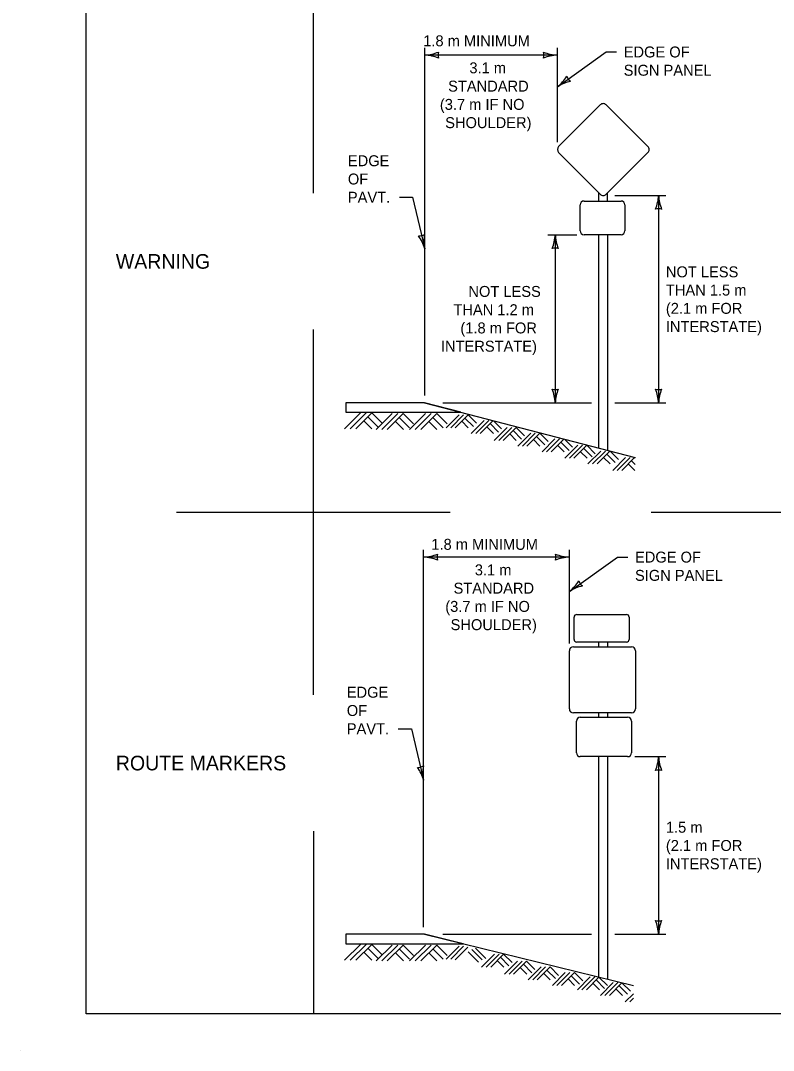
# Model space of a CAD drawing. Extents: x 49991.4 to 50021, y 49987.6 to 50011.4.
# Drawn here: x 49999.02 to 50003.15, y 49987.6 to 49993.24 of the extents above; entities that cross this region are included whole.
import ezdxf

# ---------------------------------------------------------------- set-up
doc = ezdxf.new("R2010")
doc.units = 0
for name, color, linetype in [('Level 1', 7, 'Continuous'), ('Level 2', 7, 'Continuous'), ('Level 3', 7, 'Continuous')]:
    doc.layers.add(name, color=color, linetype=linetype)

msp = doc.modelspace()

# ---------------------------------------------------------------- linework, layer by layer
at = {"layer": 'Level 1'}
for p, q in [((50001.9717, 49992.5484), (50002.2003, 49992.7772)), ((50002.2321, 49992.7772), (50002.461, 49992.5484)), ((50002.2003, 49992.2877), (50001.9717, 49992.5166)), ((50002.461, 49992.5166), (50002.2321, 49992.2877)), ((50002.1919, 49992.2506), (50002.1919, 49992.2961)), ((50002.2405, 49992.2506), (50002.2405, 49992.2961)), ((50002.0896, 49992.0878), (50002.0896, 49992.2291)), ((50002.1111, 49992.2506), (50002.3137, 49992.2506)), ((50002.3352, 49992.2291), (50002.3352, 49992.0878)), ((50002.3137, 49992.0663), (50002.1111, 49992.0663)), ((50002.1919, 49990.8971), (50002.1919, 49992.0663)), ((50002.2406, 49990.8844), (50002.2406, 49992.0663)), ((50000.7994, 49991.003), (50000.8867, 49991.0903)), ((50001.2376, 49991.1452), (50000.8056, 49991.1452)), ((50000.8056, 49991.1452), (50000.8056, 49991.0936)), ((50001.2376, 49991.1452), (50000.8056, 49991.1452)), ((50000.8056, 49991.1452), (50000.8056, 49991.0936)), ((50000.8056, 49991.0936), (50001.4364, 49991.0936)), ((50000.8056, 49991.0936), (50001.4363, 49991.0936)), ((50000.8301, 49991.003), (50000.9174, 49991.0903)), ((50000.8605, 49991.003), (50000.9478, 49991.0903)), ((50000.9478, 49991.0903), (50001.0047, 49991.0335)), ((50001.2379, 49991.1452), (50002.3914, 49990.8452)), ((50001.4363, 49991.0936), (50001.2379, 49991.1452)), ((50001.4361, 49991.0936), (50001.4361, 49991.0936)), ((50000.9047, 49991.047), (50000.9488, 49991.003)), ((50000.9264, 49991.0687), (50000.9831, 49991.0121)), ((50000.9722, 49990.9993), (50001.0595, 49991.0867)), ((50001.0029, 49990.9993), (50001.0902, 49991.0867)), ((50001.0334, 49990.9993), (50001.1207, 49991.0867)), ((50001.0775, 49991.0434), (50001.1216, 49990.9993)), ((50001.0991, 49991.0651), (50001.1558, 49991.0084)), ((50001.1207, 49991.0867), (50001.1776, 49991.0299)), ((50001.1557, 49990.9993), (50001.243, 49991.0867)), ((50001.1864, 49990.9993), (50001.2737, 49991.0867)), ((50001.2168, 49990.9993), (50001.3042, 49991.0867)), ((50001.261, 49991.0434), (50001.3051, 49990.9993)), ((50001.2826, 49991.0651), (50001.3393, 49991.0084)), ((50001.3042, 49991.0867), (50001.3611, 49991.0299)), ((50001.356, 49991.0088), (50001.4267, 49991.0795)), ((50001.3808, 49991.0088), (50001.4515, 49991.0795)), ((50001.4054, 49991.0088), (50001.4761, 49991.0795)), ((50001.4412, 49991.0446), (50001.4771, 49991.0088)), ((50001.4587, 49991.0622), (50001.5048, 49991.0162)), ((50001.4761, 49991.0795), (50001.5222, 49991.0335)), ((50001.4934, 49990.9781), (50001.5641, 49991.0488)), ((50001.5182, 49990.9781), (50001.5889, 49991.0488)), ((50001.5428, 49990.9781), (50001.6126, 49991.0477)), ((50001.6155, 49991.047), (50001.6596, 49991.0028)), ((50001.5786, 49991.0138), (50001.6145, 49990.9781)), ((50001.5962, 49991.0315), (50001.6422, 49990.9855)), ((50001.6191, 49990.9398), (50001.6898, 49991.0105)), ((50001.644, 49990.9398), (50001.7147, 49991.0105)), ((50001.6686, 49990.9398), (50001.7393, 49991.0105)), ((50001.722, 49990.9931), (50001.7679, 49990.9472)), ((50001.7393, 49991.0105), (50001.7854, 49990.9645)), ((50001.7482, 49990.908), (50001.8189, 49990.9788)), ((50001.7732, 49990.908), (50001.8439, 49990.9788)), ((50001.7978, 49990.908), (50001.8685, 49990.9788)), ((50001.8685, 49990.9788), (50001.9146, 49990.9327)), ((50001.7044, 49990.9756), (50001.7402, 49990.9398)), ((50001.8336, 49990.9437), (50001.8693, 49990.908)), ((50001.851, 49990.9614), (50001.897, 49990.9154)), ((50001.881, 49990.8776), (50001.9517, 49990.9483)), ((50001.9058, 49990.8776), (50001.9767, 49990.9483)), ((50001.9306, 49990.8776), (50002, 49990.947)), ((50001.9838, 49990.9308), (50002.0298, 49990.8851)), ((50002.0035, 49990.9461), (50002.0474, 49990.9024)), ((50001.9664, 49990.9132), (50002.002, 49990.8776)), ((50002.0065, 49990.8418), (50002.0772, 49990.9126)), ((50002.0315, 49990.8418), (50002.1022, 49990.9126)), ((50002.056, 49990.8418), (50002.1267, 49990.9126)), ((50002.0918, 49990.8776), (50002.1275, 49990.8418)), ((50002.1092, 49990.8951), (50002.1553, 49990.8492)), ((50002.1267, 49990.9126), (50002.1729, 49990.8665)), ((50002.1328, 49990.8107), (50002.2035, 49990.8814)), ((50002.1576, 49990.8107), (50002.2284, 49990.8814)), ((50002.1822, 49990.8107), (50002.2529, 49990.8812)), ((50002.2356, 49990.864), (50002.2816, 49990.8181)), ((50002.2534, 49990.8811), (50002.2992, 49990.8355)), ((50002.2181, 49990.8464), (50002.2538, 49990.8107)), ((50002.2681, 49990.7748), (50002.3388, 49990.8455)), ((50002.2931, 49990.7748), (50002.3638, 49990.8455)), ((50002.3176, 49990.7748), (50002.3884, 49990.8455)), ((50002.3535, 49990.8105), (50002.3893, 49990.7748)), ((50002.3709, 49990.8281), (50002.3914, 49990.8076)), ((50002.3884, 49990.8455), (50002.3914, 49990.8425)), ((50002.0565, 49989.8499), (50002.0565, 49989.9711)), ((50002.0715, 49989.9861), (50002.3436, 49989.9861)), ((50002.3586, 49989.9711), (50002.3586, 49989.8499)), ((50002.0531, 49989.8098), (50002.3707, 49989.8098)), ((50002.3436, 49989.8349), (50002.0715, 49989.8349)), ((50002.192, 49989.8098), (50002.192, 49989.8349)), ((50002.2406, 49989.8098), (50002.2406, 49989.8349)), ((50002.0306, 49989.4698), (50002.0306, 49989.7873)), ((50002.3932, 49989.7873), (50002.3932, 49989.4698)), ((50002.3707, 49989.4473), (50002.0531, 49989.4473)), ((50002.0693, 49989.229), (50002.0693, 49989.4019)), ((50002.0908, 49989.4234), (50002.35, 49989.4234)), ((50002.192, 49989.4234), (50002.192, 49989.4473)), ((50002.2406, 49989.4234), (50002.2406, 49989.4473)), ((50002.3715, 49989.4019), (50002.3715, 49989.229)), ((50002.35, 49989.2075), (50002.0908, 49989.2075)), ((50002.192, 49988.0012), (50002.192, 49989.2075)), ((50002.2406, 49987.9893), (50002.2406, 49989.2075)), ((50001.2376, 49988.2345), (50000.8056, 49988.2345)), ((50000.8056, 49988.2345), (50000.8056, 49988.1828)), ((50001.2376, 49988.2345), (50000.8056, 49988.2345)), ((50000.8056, 49988.2345), (50000.8056, 49988.1828)), ((50001.2377, 49988.2345), (50002.3813, 49987.9549)), ((50001.4491, 49988.1828), (50001.2377, 49988.2345)), ((50000.7994, 49988.0922), (50000.8867, 49988.1796)), ((50000.8056, 49988.1828), (50001.4491, 49988.1828)), ((50000.8056, 49988.1828), (50001.4491, 49988.1828)), ((50000.8301, 49988.0922), (50000.9174, 49988.1796)), ((50000.8605, 49988.0922), (50000.9479, 49988.1796)), ((50000.9264, 49988.158), (50000.9832, 49988.1013)), ((50000.9479, 49988.1796), (50001.0047, 49988.1228)), ((50000.9722, 49988.0886), (50001.0596, 49988.1759)), ((50001.0029, 49988.0886), (50001.0902, 49988.1759)), ((50001.0334, 49988.0886), (50001.1207, 49988.1759)), ((50001.1207, 49988.1759), (50001.1776, 49988.1192)), ((50001.1557, 49988.0886), (50001.2431, 49988.1759)), ((50001.1864, 49988.0886), (50001.2737, 49988.1759)), ((50001.2169, 49988.0886), (50001.3042, 49988.1759)), ((50001.3042, 49988.1759), (50001.3611, 49988.1192)), ((50001.356, 49988.0981), (50001.4267, 49988.1688)), ((50001.3808, 49988.0981), (50001.4515, 49988.1688)), ((50001.4044, 49988.0941), (50001.4751, 49988.1648)), ((50001.5157, 49988.1583), (50001.5726, 49988.1016)), ((50000.9047, 49988.1363), (50000.9488, 49988.0922)), ((50001.0775, 49988.1326), (50001.1217, 49988.0886)), ((50001.0991, 49988.1543), (50001.1559, 49988.0977)), ((50001.261, 49988.1326), (50001.3051, 49988.0886)), ((50001.2826, 49988.1543), (50001.3394, 49988.0977)), ((50001.4762, 49988.1379), (50001.5331, 49988.0812)), ((50001.4957, 49988.1519), (50001.5526, 49988.0952)), ((50001.5503, 49988.0553), (50001.621, 49988.126)), ((50001.5751, 49988.0553), (50001.6458, 49988.126)), ((50001.5998, 49988.0553), (50001.6706, 49988.126)), ((50001.6531, 49988.1086), (50001.6991, 49988.0627)), ((50001.6706, 49988.126), (50001.7166, 49988.08)), ((50001.6355, 49988.0909), (50001.6714, 49988.0553)), ((50001.676, 49988.017), (50001.7467, 49988.0877)), ((50001.7009, 49988.017), (50001.7716, 49988.0877)), ((50001.7255, 49988.017), (50001.7962, 49988.0877)), ((50001.7613, 49988.0527), (50001.7971, 49988.017)), ((50001.7789, 49988.0703), (50001.8249, 49988.0244)), ((50001.7962, 49988.0877), (50001.8423, 49988.0417)), ((50001.8051, 49987.9852), (50001.8758, 49988.056)), ((50001.8301, 49987.9852), (50001.9008, 49988.056)), ((50001.8547, 49987.9852), (50001.9254, 49988.056)), ((50001.9254, 49988.056), (50001.9715, 49988.0099)), ((50001.8905, 49988.0208), (50001.9262, 49987.9852)), ((50001.9079, 49988.0385), (50001.9539, 49987.9926)), ((50001.9379, 49987.9547), (50002.0086, 49988.0254)), ((50001.9627, 49987.9547), (50002.0336, 49988.0254)), ((50001.9875, 49987.9547), (50002.0582, 49988.0254)), ((50002.0233, 49987.9904), (50002.0589, 49987.9547)), ((50002.0407, 49988.008), (50002.0867, 49987.9623)), ((50002.0582, 49988.0254), (50002.1043, 49987.9796)), ((50002.0746, 49987.9311), (50002.1453, 49988.0019)), ((50002.0996, 49987.9311), (50002.1703, 49988.0019)), ((50002.1241, 49987.9311), (50002.1926, 49987.9997)), ((50002.1926, 49987.9997), (50002.2388, 49987.9536)), ((50002.1599, 49987.9668), (50002.1956, 49987.9311)), ((50002.1773, 49987.9844), (50002.2234, 49987.9385)), ((50002.2009, 49987.9), (50002.2716, 49987.9707)), ((50002.2257, 49987.9), (50002.2966, 49987.9707)), ((50002.2503, 49987.9), (50002.3189, 49987.9684)), ((50002.2862, 49987.9357), (50002.3219, 49987.9)), ((50002.3037, 49987.9533), (50002.3497, 49987.9074)), ((50002.3189, 49987.9684), (50002.365, 49987.9225)), ((50002.3362, 49987.8641), (50002.3813, 49987.9092)), ((50002.3612, 49987.8641), (50002.3813, 49987.8842)), ((49999.0245, 49987.5988), (49999.0245, 49987.5988))]:
    msp.add_line(p, q, dxfattribs=at)
msp.add_lwpolyline([(49999.3835, 49998.9992), (50016.7501, 49998.9992), (50016.7501, 49987.7988), (49999.3835, 49987.7988)], close=True, dxfattribs=at)
for centre, radius, start, end in [((50002.2162, 49992.7613), 0.0225, 45.011, 135.022), ((50001.9876, 49992.5325), 0.0225, 135.022, 224.967), ((50002.4451, 49992.5325), 0.0225, 315, 45.011), ((50002.2162, 49992.3036), 0.0225, 224.967, 315), ((50002.1111, 49992.2291), 0.0215, 90, 180), ((50002.3137, 49992.2291), 0.0215, 0, 90), ((50002.1111, 49992.0878), 0.0215, 180, 270), ((50002.3137, 49992.0878), 0.0215, 270, 0), ((50002.0715, 49989.9711), 0.015, 90, 180), ((50002.3436, 49989.9711), 0.015, 0, 90), ((50002.0715, 49989.8499), 0.015, 180, 270), ((50002.3436, 49989.8499), 0.015, 270, 0), ((50002.0531, 49989.7873), 0.0225, 90, 180), ((50002.3707, 49989.7873), 0.0225, 0, 90), ((50002.0531, 49989.4698), 0.0225, 180, 270), ((50002.3707, 49989.4698), 0.0225, 270, 0), ((50002.0908, 49989.4019), 0.0215, 90, 180), ((50002.35, 49989.4019), 0.0215, 0, 90), ((50002.0908, 49989.229), 0.0215, 180, 270), ((50002.35, 49989.229), 0.0215, 270, 0)]:
    msp.add_arc(centre, radius, start, end, dxfattribs=at)
at = {"layer": 'Level 3'}
for p, q in [((50000.6286, 49992.2934), (50000.6286, 49994.2934)), ((50001.2384, 49991.1852), (50001.2384, 49993.0898)), ((50001.9651, 49992.5725), (50001.9651, 49993.0898)), ((50001.9651, 49992.876), (50002.233, 49993.0668)), ((50002.233, 49993.0668), (50002.2884, 49993.0668)), ((50001.9651, 49993.0498), (50001.2384, 49993.0498)), ((50002.2805, 49992.2811), (50002.5595, 49992.2811)), ((50002.5195, 49992.2811), (50002.5195, 49991.1446)), ((50001.0996, 49992.2711), (50001.1716, 49992.2711)), ((50001.1716, 49992.2711), (50001.2384, 49991.9896)), ((50001.9133, 49992.0663), (50002.0711, 49992.0663)), ((50001.9533, 49992.0663), (50001.9533, 49991.1446)), ((50000.6286, 49989.5461), (50000.6286, 49991.5461)), ((50001.3379, 49991.1446), (50002.1519, 49991.1446)), ((50002.2806, 49991.1446), (50002.5595, 49991.1446)), ((49999.8786, 49990.5461), (50001.3786, 49990.5461)), ((50002.4787, 49990.5461), (50003.9787, 49990.5461)), ((50001.2323, 49988.2745), (50001.2323, 49990.3404)), ((50002.0306, 49990.3004), (50001.2323, 49990.3004)), ((50002.0306, 49989.8273), (50002.0306, 49990.3404)), ((50002.0306, 49990.1122), (50002.2949, 49990.3004)), ((50002.2949, 49990.3004), (50002.3503, 49990.3004)), ((50001.0935, 49989.3604), (50001.1655, 49989.3604)), ((50001.1655, 49989.3604), (50001.2323, 49989.0789)), ((50002.39, 49989.2075), (50002.5595, 49989.2075)), ((50002.5195, 49989.2075), (50002.5195, 49988.2345)), ((50000.6286, 49988.7988), (50000.6286, 49987.7988)), ((50001.3377, 49988.2345), (50002.152, 49988.2345)), ((50002.2806, 49988.2345), (50002.5595, 49988.2345))]:
    msp.add_line(p, q, dxfattribs=at)
for centre, radius, start, end in [((50001.2269, 49993.2825), 0.233, 272.8273, 292.0772), ((50001.3666, 49993.0498), 0.0548, 162.1388, 197.8612), ((50001.9743, 49993.2719), 0.2223, 247.456, 267.6395), ((50001.8369, 49993.0498), 0.0548, 342.1388, 17.8612), ((50001.2292, 49992.8277), 0.2223, 67.456, 87.6395), ((50001.9766, 49992.8171), 0.233, 92.8273, 112.0772), ((50001.8207, 49993.0589), 0.233, 308.286, 327.5359), ((50002.0865, 49992.6898), 0.2223, 102.9147, 123.0982), ((50002.0695, 49992.9504), 0.0548, 197.5975, 233.3199), ((50002.2974, 49992.2903), 0.2223, 337.456, 357.6395), ((50002.7522, 49992.2926), 0.233, 182.8273, 202.0772), ((50002.5195, 49992.1529), 0.0548, 72.1388, 107.8612), ((50001.2088, 49992.1144), 0.0548, 265.4882, 301.2106), ((50001.0146, 49991.9247), 0.233, 16.1767, 35.4265), ((50001.4566, 49992.032), 0.2223, 170.8054, 190.9889), ((50001.7312, 49992.0755), 0.2223, 337.456, 357.6395), ((50002.186, 49992.0778), 0.233, 182.8273, 202.0772), ((50001.9533, 49991.9381), 0.0548, 72.1388, 107.8612), ((50001.9533, 49991.2728), 0.0548, 252.1388, 287.8612), ((50001.7206, 49991.1331), 0.233, 2.8273, 22.0772), ((50002.1754, 49991.1354), 0.2223, 157.456, 177.6395), ((50002.5195, 49991.2728), 0.0548, 252.1388, 287.8612), ((50002.2868, 49991.1331), 0.233, 2.8273, 22.0772), ((50002.7416, 49991.1354), 0.2223, 157.456, 177.6395), ((50001.2208, 49990.5331), 0.233, 272.8273, 292.0772), ((50001.2231, 49990.0783), 0.2223, 67.456, 87.6395), ((50001.3605, 49990.3004), 0.0548, 162.1388, 197.8612), ((50002.0398, 49990.5225), 0.2223, 247.456, 267.6395), ((50001.9024, 49990.3004), 0.0548, 342.1388, 17.8612), ((50002.0421, 49990.0677), 0.233, 92.8273, 112.0772), ((50001.8863, 49990.2951), 0.233, 308.2808, 327.5307), ((50002.152, 49989.9259), 0.2223, 102.9095, 123.093), ((50002.135, 49990.1866), 0.0548, 197.5923, 233.3147), ((50002.2974, 49989.2167), 0.2223, 337.456, 357.6395), ((50002.7522, 49989.219), 0.233, 182.8273, 202.0772), ((50001.2027, 49989.2037), 0.0548, 265.4882, 301.2106), ((50001.0085, 49989.014), 0.233, 16.1767, 35.4265), ((50001.4505, 49989.1213), 0.2223, 170.8054, 190.9889), ((50002.5195, 49989.0793), 0.0548, 72.1388, 107.8612), ((50002.5195, 49988.3627), 0.0548, 252.1388, 287.8612), ((50002.2868, 49988.223), 0.233, 2.8273, 22.0772), ((50002.7416, 49988.2253), 0.2223, 157.456, 177.6395)]:
    msp.add_arc(centre, radius, start, end, dxfattribs=at)

# ---------------------------------------------------------------- texts
at = {"layer": 'Level 2'}
for s, height, p in [('1.8 m MINIMUM', 0.06, (50001.2303, 49993.0979)), ('EDGE OF', 0.06, (50002.3284, 49993.0368)), ('3.1 m', 0.06, (50001.4831, 49992.9498)), ('SIGN PANEL', 0.06, (50002.3284, 49992.9368)), ('STANDARD', 0.06, (50001.3666, 49992.8498)), ('(3.7 m IF NO', 0.06, (50001.3214, 49992.7498)), ('SHOULDER)', 0.06, (50001.3506, 49992.6498)), ('EDGE', 0.06, (50000.8175, 49992.4411)), ('OF', 0.06, (50000.8175, 49992.3411)), ('PAVT.', 0.06, (50000.8175, 49992.2411)), ('WARNING', 0.08, (49999.5462, 49991.8798)), ('NOT LESS', 0.06, (50002.5595, 49991.8328)), ('NOT LESS', 0.06, (50001.4776, 49991.7254)), ('THAN 1.5 m', 0.06, (50002.5595, 49991.7328)), ('THAN 1.2 m', 0.06, (50001.3955, 49991.6254)), ('(2.1 m FOR', 0.06, (50002.5595, 49991.6328)), ('(1.8 m FOR', 0.06, (50001.4339, 49991.5254)), ('INTERSTATE)', 0.06, (50002.5595, 49991.5328)), ('INTERSTATE)', 0.06, (50001.3271, 49991.4254)), ('1.8 m MINIMUM', 0.06, (50001.2747, 49990.3404)), ('EDGE OF', 0.06, (50002.3903, 49990.2704)), ('3.1 m', 0.06, (50001.5127, 49990.2004)), ('SIGN PANEL', 0.06, (50002.3903, 49990.1704)), ('STANDARD', 0.06, (50001.3962, 49990.1004)), ('(3.7 m IF NO', 0.06, (50001.351, 49990.0004)), ('SHOULDER)', 0.06, (50001.3802, 49989.9004)), ('EDGE', 0.06, (50000.8114, 49989.5304)), ('OF', 0.06, (50000.8114, 49989.4304)), ('PAVT.', 0.06, (50000.8114, 49989.3304)), ('ROUTE MARKERS', 0.08, (49999.5462, 49989.1325)), ('1.5 m', 0.06, (50002.5595, 49988.791)), ('(2.1 m FOR', 0.06, (50002.5595, 49988.691)), ('INTERSTATE)', 0.06, (50002.5595, 49988.591))]:
    msp.add_text(s, height=height, dxfattribs=at).set_placement(p)

doc.saveas('drawing.dxf')
